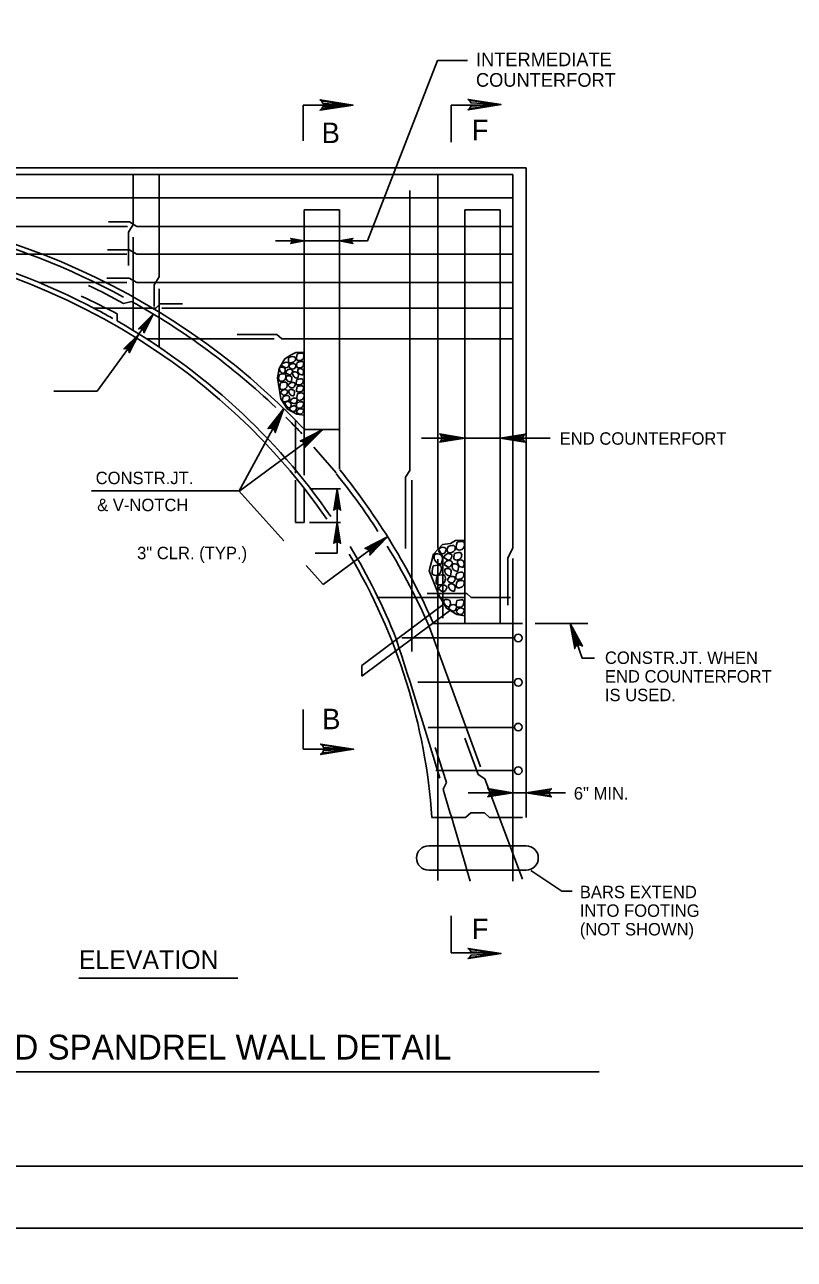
# Model space of a CAD drawing. Extents: x 639028 to 639883, y 298843 to 300031.
# Drawn here: x 639192.5 to 639378.6, y 299429.6 to 299727.9 of the extents above; entities that cross this region are included whole.
import ezdxf

# ---------------------------------------------------------------- set-up
doc = ezdxf.new("R2010")
doc.units = 0
for name, color, linetype in [('2', 7, 'Continuous'), ('52', 7, 'Continuous'), ('53', 7, 'Continuous'), ('PLT-BNDY', 7, 'Continuous')]:
    doc.layers.add(name, color=color, linetype=linetype)

msp = doc.modelspace()

# ---------------------------------------------------------------- linework, layer by layer
at = {"layer": '2'}
for p, q in [((639259.8, 299708.48), (639259.8, 299699.82)), ((639259.8, 299708.48), (639269.84, 299708.48)), ((639295.59, 299708.48), (639295.59, 299699.54)), ((639295.59, 299708.48), (639305.36, 299708.48)), ((639313.78, 299693.35), (639130.28, 299693.35)), ((639310.54, 299691.7), (639130.28, 299691.7)), ((639218.69, 299679.6), (639218.69, 299691.7)), ((639225.02, 299672.87), (639225.02, 299691.7)), ((639292.39, 299601.5), (639292.39, 299691.7)), ((639310.54, 299684.83), (639310.54, 299691.7)), ((639313.78, 299536.33), (639313.78, 299693.35)), ((639310.54, 299686.07), (639130.28, 299686.07)), ((639285.65, 299620.2), (639285.65, 299687.85)), ((639268.6, 299683.18), (639260.08, 299683.18)), ((639260.08, 299630.1), (639260.08, 299683.18)), ((639268.6, 299620.48), (639268.6, 299683.18)), ((639307.45, 299683.18), (639298.92, 299683.18)), ((639298.92, 299583.22), (639298.92, 299683.18)), ((639307.45, 299583.22), (639307.45, 299683.18)), ((639310.54, 299601.5), (639310.54, 299684.83)), ((639217.32, 299679.19), (639130.28, 299679.19)), ((639217.87, 299680.29), (639212.78, 299680.29)), ((639218.69, 299679.6), (639217.59, 299677.82)), ((639217.87, 299680.29), (639219.65, 299679.19)), ((639310.54, 299679.19), (639219.65, 299679.19)), ((639217.59, 299669.7), (639217.59, 299677.82)), ((639218.69, 299654.03), (639218.69, 299676.58)), ((639217.73, 299673.55), (639212.5, 299673.55)), ((639217.73, 299673.55), (639219.65, 299672.45)), ((639217.18, 299672.45), (639176.2, 299672.45)), ((639310.54, 299672.45), (639219.65, 299672.45)), ((639225.02, 299666.95), (639225.02, 299673)), ((639217.18, 299665.58), (639196, 299665.58)), ((639217.73, 299666.68), (639212.37, 299666.68)), ((639217.73, 299666.68), (639219.65, 299665.58)), ((639310.54, 299665.58), (639219.65, 299665.58)), ((639225.02, 299666.95), (639223.78, 299665.03)), ((639223.78, 299659.8), (639223.78, 299665.03)), ((639225.02, 299650.04), (639225.02, 299664.07)), ((639224.19, 299659.39), (639209.2, 299659.39)), ((639209.75, 299659.12), (639211.13, 299658.43)), ((639218.42, 299661.04), (639216.42, 299660.54)), ((639224.19, 299659.39), (639225.29, 299660.49)), ((639230.65, 299660.49), (639225.29, 299660.49)), ((639310.54, 299659.39), (639225.7, 299659.39)), ((639223.64, 299658.02), (639210.03, 299639.32)), ((639214.84, 299656.37), (639214.84, 299658.01)), ((639253.48, 299653.07), (639243.85, 299653.07)), ((639253.48, 299653.07), (639254.72, 299651.97)), ((639252.79, 299651.97), (639221.99, 299651.97)), ((639310.54, 299651.97), (639254.72, 299651.97)), ((639210.03, 299639.32), (639199.58, 299639.32)), ((639255.13, 299635.19), (639244.27, 299615.12)), ((639258.02, 299619.56), (639258.02, 299632.38)), ((639264.62, 299630.1), (639244.27, 299615.12)), ((639259.25, 299629.42), (639259.55, 299629.07)), ((639268.6, 299630.1), (639260.08, 299630.1)), ((639260.08, 299619.1), (639260.08, 299630.1)), ((639262.38, 299625.84), (639267.78, 299619.65)), ((639284.55, 299618.55), (639285.65, 299620.2)), ((639258.02, 299607.59), (639258.02, 299617.85)), ((639284.55, 299601.37), (639284.55, 299618.55)), ((639286.15, 299576.48), (639286.15, 299617.87)), ((639244.4, 299615.25), (639208.65, 299615.25)), ((639255.14, 299603.2), (639244.27, 299615.25)), ((639260.08, 299607.59), (639260.08, 299615.79)), ((639268.07, 299615.64), (639268.07, 299600.18)), ((639258.02, 299607.59), (639260.08, 299607.59)), ((639280.27, 299604.15), (639264.65, 299592.65)), ((639292.39, 299601.5), (639293.63, 299599.3)), ((639310.54, 299601.5), (639309.3, 299599.03)), ((639292.39, 299521.14), (639292.39, 299598.75)), ((639293.63, 299584.49), (639293.63, 299599.3)), ((639309.3, 299587.62), (639309.3, 299599.03)), ((639310.54, 299520.97), (639310.54, 299598.89)), ((639264.65, 299592.65), (639260.53, 299597.21)), ((639289.8, 299590.5), (639299.4, 299590.5)), ((639299.4, 299590.5), (639300.5, 299589.54)), ((639274.02, 299573.07), (639293.96, 299587.96)), ((639277.68, 299589.54), (639298.72, 299589.54)), ((639300.5, 299589.54), (639309.99, 299589.54)), ((639274.02, 299570.49), (639295.19, 299586.31)), ((639290.33, 299582.53), (639302.7, 299548.57)), ((639291.29, 299583.22), (639312.88, 299583.22)), ((639315.95, 299583.22), (639328.67, 299583.22)), ((639283.69, 299579.72), (639310.82, 299579.72)), ((639274.02, 299570.49), (639274.02, 299573.07)), ((639287.56, 299569.01), (639310.36, 299569.01)), ((639259.8, 299562.45), (639259.8, 299552.83)), ((639290.07, 299558.06), (639310.82, 299558.06)), ((639298.91, 299555.51), (639302.19, 299546.71)), ((639259.8, 299552.83), (639269.84, 299552.83)), ((639291.76, 299553.29), (639294.51, 299544.77)), ((639291.9, 299547.69), (639310.82, 299547.69)), ((639303.8, 299545.68), (639302.19, 299546.71)), ((639303.8, 299545.68), (639312.91, 299521.47)), ((639293.69, 299543.16), (639294.51, 299544.77)), ((639290.98, 299536.33), (639299.13, 299536.33)), ((639299.13, 299536.33), (639300.37, 299537.43)), ((639300.37, 299537.43), (639303.67, 299537.43)), ((639303.67, 299537.43), (639304.9, 299536.33)), ((639304.9, 299536.33), (639312.88, 299536.33)), ((639290.19, 299529.48), (639313.77, 299529.48)), ((639313.77, 299523.63), (639290.19, 299523.63)), ((639295.59, 299503.61), (639295.59, 299512.55)), ((639295.59, 299503.61), (639305.36, 299503.61)), ((639853.74, 299452.08), (639067.74, 299452.08))]:
    msp.add_line(p, q, dxfattribs=at)
for points in [[(639264.34, 299709.44), (639264.62, 299708.89), (639271.9, 299708.48), (639264.34, 299709.44), (639263.93, 299709.72), (639271.9, 299708.48), (639264.62, 299708.07), (639264.34, 299707.65), (639271.9, 299708.48), (639263.93, 299707.24), (639264.34, 299707.65)], [(639300.13, 299709.58), (639300.41, 299709.03), (639307.69, 299708.62), (639300.13, 299709.58), (639299.72, 299709.85), (639307.69, 299708.62), (639300.41, 299708.2), (639300.13, 299707.65), (639307.69, 299708.62), (639299.72, 299707.38), (639300.13, 299707.65)], [(639254.03, 299640.14), (639254.03, 299640.14)], [(639259.39, 299633.68), (639259.39, 299633.68)], [(639292.27, 299593.01), (639292.27, 299593.01)], [(639298.17, 299585.25), (639298.17, 299585.25)], [(639264.48, 299553.79), (639264.75, 299553.24), (639272.04, 299552.83), (639264.48, 299553.79), (639264.07, 299554.07), (639272.04, 299552.83), (639264.75, 299552.55), (639264.48, 299552), (639272.04, 299552.83), (639264.07, 299551.59), (639264.48, 299552)], [(639300.13, 299502.51), (639300.41, 299503.06), (639307.69, 299503.47), (639300.13, 299502.51), (639299.72, 299502.24), (639307.69, 299503.47), (639300.41, 299503.89), (639300.13, 299504.44), (639307.69, 299503.47), (639299.72, 299504.71), (639300.13, 299504.44)]]:
    msp.add_lwpolyline(points, dxfattribs=at)
for points in [[(639260.07, 299648.75), (639260.08, 299633.54), (639258.29, 299633.82), (639256.09, 299635.05), (639254.44, 299637.53), (639253.62, 299642.62), (639254.03, 299644.82), (639255.4, 299647.15), (639256.92, 299648.12), (639258.05, 299648.72)], [(639298.92, 299603.34), (639298.92, 299585.09), (639296.96, 299585.42), (639294.54, 299586.9), (639292.72, 299589.87), (639290.3, 299595.97), (639291.37, 299599.98), (639293.5, 299602.3), (639295.44, 299602.58), (639296.69, 299603.3)]]:
    msp.add_lwpolyline(points, close=True, dxfattribs=at)
for centre, radius, start, end in [((637630.31, 299042.75), 1737.02, 16.83625, 18.00083), ((637630.31, 299042.75), 1737.02, 15.97991, 16.74331), ((639290.19, 299526.56), 2.93, 90, 270), ((639313.77, 299526.56), 2.93, 270, 90)]:
    msp.add_arc(centre, radius, start, end, dxfattribs=at)
for centre, major_axis, ratio, start_param, end_param in [((639130.23, 299520.96), (-174.13, 0), 0.941368, 3.870612, 4.712389), ((639130.23, 299520.96), (-172.99, 0), 0.940984, 4.190973, 4.712389), ((639130.23, 299526.64), (-162.22, 0), 0.937063, 4.199675, 4.712389), ((639130.23, 299526.64), (-161.08, 0), 0.93662, 3.714425, 4.712389), ((639129.95, 299520.85), (-171.86, 0), 0.940594, 4.185118, 4.241474), ((639133.97, 299524.96), (-163.35, 0), 0.9375, 4.194452, 4.254411), ((639130.23, 299526.64), (-162.22, 0), 0.937063, 4.171046, 4.190527), ((639130.23, 299520.96), (-172.99, 0), 0.940984, 3.921266, 4.177888), ((639130.23, 299526.64), (-162.22, 0), 0.937063, 3.714715, 4.163754), ((639130.23, 299520.96), (-172.99, 0), 0.940984, 3.870612, 3.901586), ((639130.23, 299520.75), (-172.99, 0), 0.940984, 3.689107, 3.793048), ((639130.23, 299520.96), (-174.13, 0), 0.941368, 3.530741, 3.793048), ((639130.23, 299526.64), (-162.22, 0), 0.937063, 3.497123, 3.658872), ((639130.23, 299520.75), (-172.99, 0), 0.940984, 3.530741, 3.663513), ((639130.23, 299526.64), (-161.08, 0), 0.93662, 3.20589, 3.649307)]:
    msp.add_ellipse(centre, major_axis=major_axis, ratio=ratio, start_param=start_param, end_param=end_param, dxfattribs=at)
for points in [[(639254.71, 299645.82), (639255.45, 299646.31), (639256.44, 299646.07), (639255.95, 299645.08), (639254.71, 299645.57)], [(639256.41, 299647.51), (639257.9, 299647.51), (639257.9, 299646.77), (639257.16, 299646.28), (639256.41, 299646.28), (639256.41, 299647.51)], [(639258.41, 299648.36), (639259.9, 299648.36), (639259.9, 299647.37), (639259.4, 299646.88), (639258.41, 299646.88), (639258.41, 299648.36)], [(639258.41, 299646.32), (639259.89, 299646.32), (639259.89, 299645.58), (639259.4, 299645.08), (639258.41, 299645.08), (639258.41, 299646.32)], [(639254.09, 299643.38), (639255.57, 299643.38), (639255.57, 299642.39), (639255.08, 299641.89), (639254.09, 299641.89), (639254.09, 299643.38)], [(639255.33, 299643.63), (639254.35, 299644.02), (639254.19, 299645.02), (639255.3, 299644.96), (639255.33, 299643.63)], [(639255.55, 299643.89), (639256.3, 299644.63), (639257.29, 299644.38), (639256.79, 299643.39), (639255.55, 299643.89)], [(639256.34, 299645.23), (639257.08, 299645.98), (639258.07, 299645.73), (639257.57, 299644.74), (639256.34, 299645.23)], [(639258.53, 299642.5), (639257.55, 299642.89), (639257.39, 299643.89), (639258.49, 299643.83), (639258.53, 299642.5)], [(639259.75, 299643.25), (639258.78, 299643.64), (639258.61, 299644.65), (639259.72, 299644.58), (639259.75, 299643.25)], [(639254.37, 299641.34), (639255.85, 299641.34), (639255.85, 299640.35), (639255.36, 299639.85), (639254.37, 299639.85), (639254.37, 299641.34)], [(639256.93, 299641.56), (639255.95, 299641.95), (639255.79, 299642.95), (639256.9, 299642.89), (639256.93, 299641.56)], [(639256.18, 299640.69), (639256.92, 299641.43), (639257.91, 299641.18), (639257.42, 299640.19), (639256.18, 299640.69)], [(639258.29, 299642.15), (639259.78, 299642.15), (639259.78, 299641.41), (639259.04, 299640.92), (639258.29, 299640.92), (639258.29, 299642.15)], [(639258.39, 299640.46), (639259.87, 299640.46), (639259.87, 299639.72), (639259.13, 299639.22), (639258.39, 299639.22), (639258.39, 299640.46)], [(639254.33, 299638.93), (639255.07, 299639.68), (639256.06, 299639.43), (639255.57, 299638.44), (639254.33, 299638.93)], [(639255, 299638.08), (639256.49, 299638.08), (639256.49, 299637.34), (639255.74, 299636.84), (639255, 299636.84), (639255, 299638.08)], [(639257.59, 299638.23), (639256.61, 299638.62), (639256.45, 299639.63), (639257.55, 299639.57), (639257.59, 299638.23)], [(639256.65, 299636.9), (639257.39, 299637.64), (639258.38, 299637.39), (639257.89, 299636.4), (639256.65, 299636.9)], [(639258.47, 299638.74), (639259.96, 299638.74), (639259.96, 299637.75), (639259.46, 299637.25), (639258.47, 299637.25), (639258.47, 299638.74)], [(639256.74, 299635.32), (639255.77, 299635.71), (639255.6, 299636.71), (639256.71, 299636.65), (639256.74, 299635.32)], [(639256.49, 299635.01), (639257.24, 299635.76), (639258.23, 299635.51), (639257.73, 299634.52), (639256.49, 299635.01)], [(639258.35, 299636.6), (639259.83, 299636.6), (639259.83, 299635.86), (639259.34, 299635.36), (639258.35, 299635.36), (639258.35, 299636.6)], [(639258.16, 299634.32), (639258.9, 299635.07), (639259.89, 299634.82), (639259.39, 299633.83), (639258.16, 299634.32)], [(639292.45, 299601.01), (639293.27, 299601.61), (639294.36, 299601.31), (639293.82, 299600.12), (639292.45, 299600.72)], [(639294.89, 299601.86), (639296.52, 299601.86), (639296.52, 299600.97), (639295.71, 299600.37), (639294.89, 299600.37), (639294.89, 299601.86)], [(639297.09, 299602.87), (639298.72, 299602.87), (639298.72, 299601.69), (639298.18, 299601.09), (639297.09, 299601.09), (639297.09, 299602.87)], [(639293.19, 299597.5), (639291.89, 299598.18), (639291.67, 299599.92), (639293.14, 299599.8), (639293.19, 299597.5)], [(639293.87, 299599.18), (639294.68, 299600.07), (639295.77, 299599.78), (639295.23, 299598.59), (639293.87, 299599.18)], [(639296.46, 299600.17), (639298.09, 299600.17), (639298.09, 299599.28), (639297.55, 299598.69), (639296.46, 299598.69), (639296.46, 299600.17)], [(639298.56, 299596.74), (639297.49, 299597.21), (639297.31, 299598.42), (639298.53, 299598.34), (639298.56, 299596.74)], [(639291.3, 299597.13), (639293.1, 299597.13), (639293.1, 299595.7), (639292.5, 299594.99), (639291.3, 299594.99), (639291.3, 299597.13)], [(639293.94, 299597.5), (639294.76, 299598.39), (639295.85, 299598.1), (639295.31, 299596.91), (639293.94, 299597.5)], [(639295.46, 299594.71), (639294.39, 299595.17), (639294.21, 299596.38), (639295.42, 299596.31), (639295.46, 299594.71)], [(639297.22, 299595.84), (639296.14, 299596.3), (639295.97, 299597.51), (639297.18, 299597.43), (639297.22, 299595.84)], [(639296.96, 299595.42), (639298.59, 299595.42), (639298.59, 299594.53), (639297.78, 299593.94), (639296.96, 299593.94), (639296.96, 299595.42)], [(639292.28, 299594.79), (639294.08, 299594.79), (639294.08, 299593.37), (639293.48, 299592.66), (639292.28, 299592.66), (639292.28, 299594.79)], [(639292.6, 299591.56), (639293.42, 299592.45), (639294.51, 299592.15), (639293.96, 299590.97), (639292.6, 299591.56)], [(639294.63, 299593.67), (639295.45, 299594.56), (639296.54, 299594.26), (639296, 299593.07), (639294.63, 299593.67)], [(639296.37, 299590.97), (639295.3, 299591.44), (639295.12, 299592.65), (639296.33, 299592.57), (639296.37, 299590.97)], [(639297.06, 299593.39), (639298.7, 299593.39), (639298.7, 299592.5), (639297.88, 299591.91), (639297.06, 299591.91), (639297.06, 299593.39)], [(639295.25, 299587.22), (639294.18, 299587.69), (639294, 299588.9), (639295.21, 299588.82), (639295.25, 299587.22)], [(639294.98, 299586.86), (639295.8, 299587.75), (639296.89, 299587.45), (639296.34, 299586.26), (639294.98, 299586.86)], [(639297.02, 299588.76), (639298.65, 299588.76), (639298.65, 299587.87), (639298.1, 299587.27), (639297.02, 299587.27), (639297.02, 299588.76)], [(639296.81, 299586.03), (639297.62, 299586.92), (639298.71, 299586.62), (639298.17, 299585.44), (639296.81, 299586.03)]]:
    msp.add_spline(points, degree=3, dxfattribs=at)
at = {"layer": '52'}
for p, q in [((639253.12, 299675.67), (639275.38, 299675.67)), ((639299.7, 299542.34), (639310.54, 299542.34)), ((639310.54, 299542.34), (639313.78, 299542.34)), ((639313.78, 299542.34), (639323.3, 299542.34)), ((639314.89, 299523.57), (639322.39, 299518.51)), ((639322.39, 299518.51), (639324.89, 299518.51))]:
    msp.add_line(p, q, dxfattribs=at)
for points in [[(639275.38, 299675.67), (639292.34, 299719.23), (639299.6, 299719.23)], [(639260.08, 299675.67), (639256.8, 299675.05), (639256.92, 299675.14), (639257.05, 299675.23), (639257.11, 299675.34), (639257.18, 299675.45), (639257.2, 299675.56), (639257.22, 299675.67), (639257.2, 299675.78), (639257.18, 299675.89), (639257.11, 299676), (639257.05, 299676.11), (639256.92, 299676.2), (639256.8, 299676.28), (639260.08, 299675.67), (639256.92, 299676.2), (639257.05, 299676.11), (639260.08, 299675.67), (639257.11, 299676), (639257.18, 299675.89), (639260.08, 299675.67), (639257.2, 299675.78), (639257.22, 299675.67), (639260.08, 299675.67), (639257.2, 299675.56), (639257.18, 299675.45), (639260.08, 299675.67), (639257.11, 299675.34), (639257.05, 299675.23), (639260.08, 299675.67), (639256.92, 299675.14)], [(639268.6, 299675.67), (639271.88, 299676.28), (639271.76, 299676.2), (639271.63, 299676.11), (639271.57, 299676), (639271.5, 299675.89), (639271.48, 299675.78), (639271.46, 299675.67), (639271.48, 299675.56), (639271.5, 299675.45), (639271.57, 299675.34), (639271.63, 299675.23), (639271.76, 299675.14), (639271.88, 299675.05), (639268.6, 299675.67), (639271.76, 299675.14), (639271.63, 299675.23), (639268.6, 299675.67), (639271.57, 299675.34), (639271.5, 299675.45), (639268.6, 299675.67), (639271.48, 299675.56), (639271.46, 299675.67), (639268.6, 299675.67), (639271.48, 299675.78), (639271.5, 299675.89), (639268.6, 299675.67), (639271.57, 299676), (639271.63, 299676.11), (639268.6, 299675.67), (639271.76, 299676.2)], [(639220.33, 299654.5), (639220.72, 299654.44), (639223.64, 299658.02), (639220.33, 299654.5), (639220.02, 299654.42), (639223.64, 299658.02), (639221.11, 299654.16), (639221.29, 299653.82), (639223.64, 299658.02), (639221.32, 299653.47), (639221.29, 299653.82)], [(639216.8, 299649.65), (639217.19, 299649.59), (639220.11, 299653.17), (639216.8, 299649.65), (639216.48, 299649.58), (639220.11, 299653.17), (639217.58, 299649.31), (639217.76, 299648.97), (639220.11, 299653.17), (639217.79, 299648.63), (639217.76, 299648.97)], [(639251.73, 299630.44), (639252.2, 299630.43), (639255.13, 299635.19), (639251.73, 299630.44), (639251.36, 299630.3), (639255.13, 299635.19), (639252.72, 299630.15), (639252.98, 299629.78), (639255.13, 299635.19), (639253.08, 299629.37), (639252.98, 299629.78)], [(639259.51, 299627.25), (639259.94, 299627.04), (639264.62, 299630.1), (639259.51, 299627.25), (639259.12, 299627.28), (639264.62, 299630.1), (639260.29, 299626.57), (639260.37, 299626.12), (639264.62, 299630.1), (639260.28, 299625.71), (639260.37, 299626.12)], [(639293.12, 299628.76), (639293.34, 299628.34), (639298.92, 299628.03), (639293.12, 299628.76), (639292.82, 299629.01), (639298.92, 299628.03), (639293.34, 299627.75), (639293.14, 299627.34), (639298.92, 299628.03), (639292.82, 299627.06), (639293.14, 299627.34)], [(639313.25, 299627.3), (639313.03, 299627.72), (639307.45, 299628.03), (639313.25, 299627.3), (639313.54, 299627.05), (639307.45, 299628.03), (639313.03, 299628.31), (639313.23, 299628.72), (639307.45, 299628.03), (639313.54, 299629), (639313.23, 299628.72)], [(639288.42, 299628.03), (639298.92, 299628.03)], [(639298.92, 299628.03), (639307.45, 299628.03)], [(639307.45, 299628.03), (639319.55, 299628.03)], [(639261.46, 299615.79), (639268.87, 299615.79)], [(639267.47, 299610.85), (639267.82, 299611.03), (639268.07, 299615.64), (639267.47, 299610.85), (639267.26, 299610.6), (639268.07, 299615.64), (639268.3, 299611.03), (639268.64, 299610.86), (639268.07, 299615.64), (639268.87, 299610.6), (639268.64, 299610.86)], [(639261.34, 299607.59), (639268.87, 299607.59)], [(639267.47, 299602.79), (639267.82, 299602.97), (639268.07, 299607.59), (639267.47, 299602.79), (639267.26, 299602.55), (639268.07, 299607.59), (639268.3, 299602.98), (639268.64, 299602.81), (639268.07, 299607.59), (639268.87, 299602.55), (639268.64, 299602.81)], [(639275.17, 299601.3), (639275.59, 299601.09), (639280.27, 299604.15), (639275.17, 299601.3), (639274.78, 299601.33), (639280.27, 299604.15), (639275.94, 299600.62), (639276.02, 299600.17), (639280.27, 299604.15), (639275.93, 299599.76), (639276.02, 299600.17)], [(639262.73, 299600.18), (639268.07, 299600.18)], [(639324.43, 299583.22), (639327.34, 299574.84), (639330.26, 299574.84)], [(639325.65, 299577.5), (639325.97, 299577.84), (639324.43, 299583.22), (639325.65, 299577.5), (639325.51, 299577.14), (639324.43, 299583.22), (639326.52, 299578.04), (639326.98, 299577.98), (639324.43, 299583.22), (639327.35, 299577.78), (639326.98, 299577.98)], [(639304.74, 299543.06), (639304.96, 299542.64), (639310.54, 299542.34), (639304.74, 299543.06), (639304.44, 299543.32), (639310.54, 299542.34), (639304.96, 299542.06), (639304.76, 299541.64), (639310.54, 299542.34), (639304.44, 299541.37), (639304.76, 299541.64)], [(639319.58, 299541.61), (639319.37, 299542.03), (639313.78, 299542.34), (639319.58, 299541.61), (639319.88, 299541.35), (639313.78, 299542.34), (639319.36, 299542.61), (639319.57, 299543.03), (639313.78, 299542.34), (639319.88, 299543.3), (639319.57, 299543.03)]]:
    msp.add_lwpolyline(points, dxfattribs=at)
for centre in [(639311.85, 299579.71), (639311.85, 299569), (639311.85, 299558.17), (639311.85, 299547.68)]:
    msp.add_circle(centre, 0.919, dxfattribs=at)
at = {"layer": '53'}
for p, q in [((639205.59, 299497.5), (639244.07, 299497.5)), ((639131.6, 299474.85), (639331.39, 299474.85))]:
    msp.add_line(p, q, dxfattribs=at)
at = {"layer": 'PLT-BNDY'}
for points in [[(639027.74, 300031.08), (639868.74, 300031.08), (639868.74, 299437.08), (639027.74, 299437.08)], [(639027.74, 299437.08), (639868.74, 299437.08), (639868.74, 298843.08), (639027.74, 298843.08)]]:
    msp.add_lwpolyline(points, close=True, dxfattribs=at)

# ---------------------------------------------------------------- texts
at = {"layer": '2'}
for s, height, p in [('INTERMEDIATE', 3.3, (639301.62, 299717.87)), ('COUNTERFORT', 3.3, (639301.62, 299712.92)), ('B', 4.95, (639264.31, 299699.31)), ('F', 4.95, (639300.63, 299699.99)), ('END COUNTERFORT', 2.9997, (639321.88, 299626.42)), ('CONSTR.JT.', 3, (639209.66, 299616.89)), ('& V-NOTCH', 3, (639210.02, 299610.37)), ('3" CLR. (TYP.)', 2.9998, (639219.68, 299598.76)), ('CONSTR.JT. WHEN', 2.9997, (639332.81, 299573.45)), ('END COUNTERFORT', 2.9997, (639332.81, 299568.95)), ('IS USED.', 3, (639332.81, 299564.45)), ('B', 4.95, (639264.45, 299557.67)), ('6" MIN.', 3, (639325.29, 299540.68)), ('BARS EXTEND', 2.9997, (639326.74, 299516.84)), ('INTO FOOTING', 2.9997, (639326.74, 299512.34)), ('F', 4.95, (639300.63, 299506.96)), ('(NOT SHOWN)', 2.9997, (639326.74, 299507.84))]:
    msp.add_text(s, height=height, dxfattribs=at).set_placement(p)
at = {"layer": '53'}
for s, height, p in [('ELEVATION', 4.5, (639205.59, 299499.75)), ('ARCH RING AND SPANDREL WALL DETAIL', 6, (639131.6, 299477.85))]:
    msp.add_text(s, height=height, dxfattribs=at).set_placement(p)

doc.saveas('drawing.dxf')
